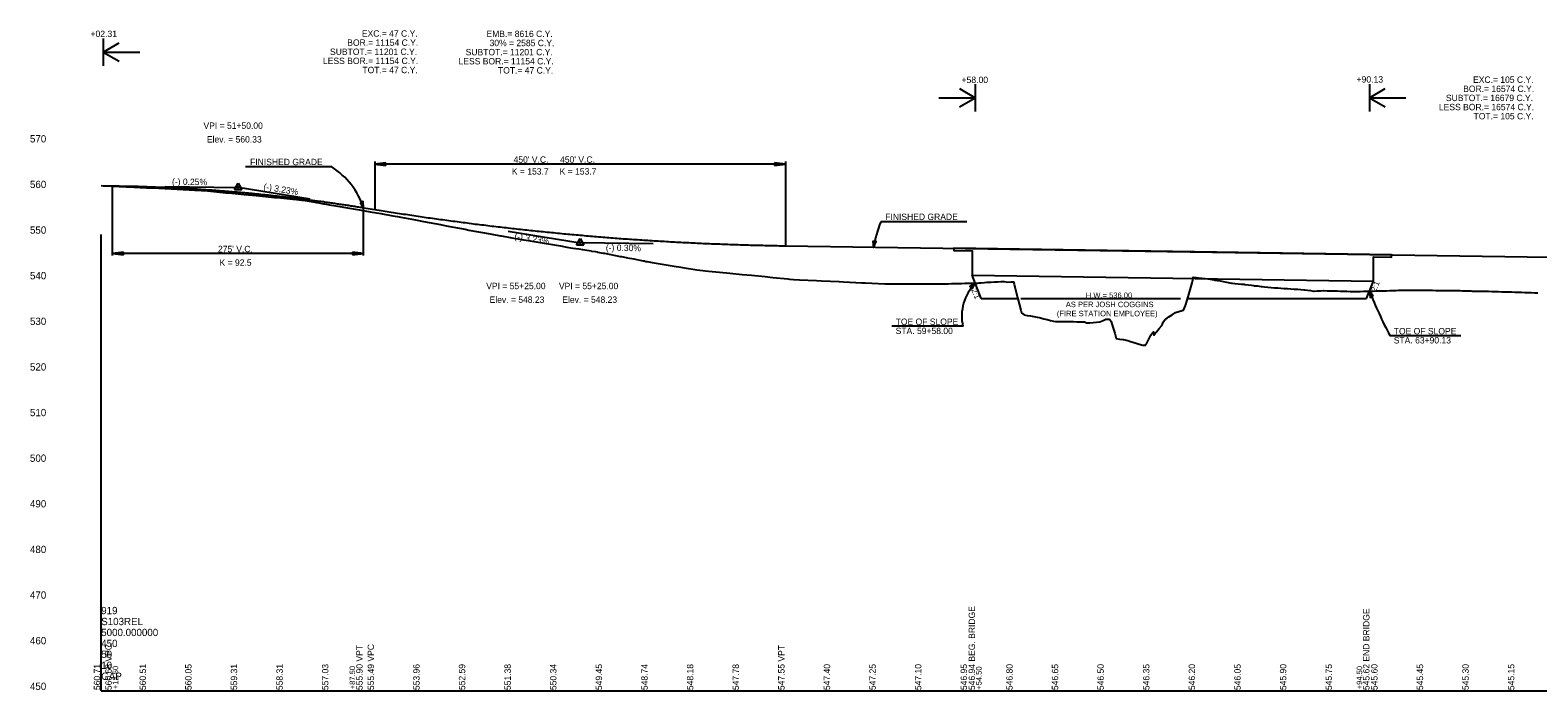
# Model space of a CAD drawing. Extents: x 49922 to 52614, y 49991 to 60509.
# Drawn here: x 49922 to 51575, y 52500 to 53224 of the extents above; entities that cross this region are included whole.
import ezdxf

# ---------------------------------------------------------------- set-up
doc = ezdxf.new("R2010")
doc.units = 0
for name, color, linetype in [('RD_DDB_ElevTX', 7, 'Continuous'), ('RD_DDB_GradeTX', 7, 'Continuous'), ('RD_DDB_Profile_EX', 7, 'Continuous'), ('RD_DDB_Profile_Lbl', 7, 'Continuous'), ('RD_DDB_Profile_PR', 7, 'Continuous'), ('RD_DDB_StripGrade', 7, 'Continuous'), ('RD_DDB_VCLbl', 7, 'Continuous'), ('RD_GPK_Profile_Cell', 7, 'Continuous'), ('RD_Sketch7', 7, 'Continuous'), ('RD_Sketch8', 7, 'Continuous'), ('RD_TX_Profile', 7, 'Continuous')]:
    doc.layers.add(name, color=color, linetype=linetype)

msp = doc.modelspace()

# ---------------------------------------------------------------- linework, layer by layer
at = {"layer": 'RD_DDB_GradeTX'}
for p, q in [((50070, 53052.7), (50150, 53051.7)), ((50146, 53049.4), (50150, 53056.3)), ((50150, 53056.3), (50154, 53049.4)), ((50229, 53038.9), (50150, 53051.7)), ((50146, 53049.4), (50154, 53049.4)), ((50446, 53003.9), (50525, 52991.1)), ((50521, 52988.8), (50525, 52995.7)), ((50521, 52988.8), (50529, 52988.8)), ((50525, 52995.7), (50529, 52988.8)), ((50605, 52989.9), (50525, 52991.1))]:
    msp.add_line(p, q, dxfattribs=at)
for centre in [(50150, 53051.7), (50525, 52991.1)]:
    msp.add_circle(centre, 0.529, dxfattribs=at)
at = {"layer": 'RD_DDB_Profile_EX'}
for points in [[(50000, 53053.7), (50004.7, 53053.4), (50027.3, 53052.4), (50029.1, 53052.3), (50049.8, 53051.4), (50052.3, 53051.3), (50053.5, 53051.2), (50056.5, 53051.1), (50063.1, 53050.8), (50069.8, 53050.5), (50076.5, 53050.1), (50077.3, 53050.1), (50077.7, 53050.1), (50083.2, 53049.8), (50085.9, 53049.7), (50089.9, 53049.5), (50096.5, 53049.2), (50102.6, 53048.8), (50103.2, 53048.8), (50109.9, 53048.4), (50111.8, 53048.3), (50113.2, 53048.2), (50116.6, 53047.9), (50123.3, 53047.2), (50130, 53046.6), (50136.7, 53045.9), (50139.3, 53045.7), (50143.3, 53045.3), (50150, 53044.7), (50156.7, 53044), (50161.6, 53043.5), (50163.4, 53043.4), (50165.7, 53043.2), (50170, 53042.8), (50176.7, 53042.1), (50183.4, 53041.4), (50186.6, 53041.1), (50190.1, 53040.8), (50192.3, 53040.6), (50196.8, 53040.2), (50203.4, 53039.5), (50210.1, 53038.9), (50211.5, 53038.7), (50214.2, 53038.5), (50216.8, 53038.2), (50219.8, 53037.9), (50223.5, 53037.3), (50230.2, 53036.2), (50236.1, 53035.3), (50236.8, 53035.1), (50243.5, 53033.9), (50244.8, 53033.7), (50250.2, 53032.8), (50259.5, 53031.3), (50269.8, 53029.4), (50283, 53027.3), (50294.8, 53025.1), (50306.4, 53023.2), (50319.8, 53020.7), (50324.6, 53019.8), (50328.3, 53019.2), (50344.6, 53016.2), (50353.2, 53014.4), (50371.8, 53011), (50378.2, 53009.7), (50399.1, 53005.8), (50403.1, 53005), (50426.5, 53000.7), (50428.1, 53000.4), (50437.7, 52998.6), (50438.3, 52998.6), (50444.7, 52997.5), (50450, 52996.6), (50456.7, 52995.4), (50462.7, 52994.4), (50463.4, 52994.3), (50468.3, 52993.5), (50470.1, 52993.1), (50476.8, 52992), (50483.4, 52990.9), (50487.6, 52990.2), (50490.1, 52989.8), (50496.8, 52988.7), (50498.9, 52988.3), (50503.5, 52987.6), (50510.2, 52986.4), (50512.5, 52986), (50516.9, 52985.3), (50523.5, 52984.3), (50527.7, 52983.6), (50530.2, 52983.2), (50536.9, 52982.1), (50537.5, 52982), (50541.9, 52981.3), (50543.6, 52981), (50544, 52980.9), (50550.3, 52979.8), (50551.6, 52979.5), (50556.9, 52978.5), (50563.6, 52977.1), (50569, 52976.1)], [(50569, 52976.1), (50570.3, 52975.9), (50575.3, 52974.9), (50577, 52974.6), (50583.7, 52973.3), (50590.3, 52972), (50594, 52971.3), (50595, 52971.1), (50597, 52970.7), (50598.6, 52970.4), (50603.9, 52969.5), (50610.4, 52968.4), (50617.1, 52967.3), (50623.7, 52966.2), (50630.4, 52965), (50633.3, 52964.6), (50637.1, 52963.9), (50643.8, 52962.8), (50648.4, 52962), (50650.7, 52961.6), (50652.7, 52961.3), (50665.5, 52960.1), (50677.7, 52958.9), (50689.1, 52957.8), (50702.7, 52956.4), (50712.7, 52955.5), (50727.7, 52954), (50736.2, 52953.1), (50752.7, 52951.5), (50754.5, 52951.3), (50758.9, 52950.9), (50765.5, 52950.6), (50783.9, 52949.7), (50789.5, 52949.5), (50808.9, 52948.5), (50813.5, 52948.3), (50833.9, 52947.3), (50837.5, 52947.2), (50859, 52946.1), (50859.3, 52946.1), (50862.3, 52945.9), (50864.8, 52946), (50887.2, 52945.9), (50895, 52946), (50912.2, 52946), (50921.2, 52946.2), (50923.2, 52946.2), (50924.8, 52946.2), (50928.4, 52946.2), (50932, 52946.3), (50935.6, 52946.3), (50937.2, 52946.3), (50939.2, 52946.4), (50942.9, 52946.5), (50946.5, 52946.6), (50950.1, 52946.7), (50951, 52946.7), (50953.7, 52946.8), (50957.3, 52946.8), (50960.9, 52946.9), (50962.2, 52947), (50963.5, 52947), (50964.5, 52947.1), (50968.1, 52947.5), (50970.8, 52947.8), (50971.7, 52947.8), (50975.4, 52948), (50979, 52948.2), (50982.6, 52948.4), (50986.2, 52948.5), (50988.7, 52948.7), (50989.8, 52948.7), (50993.6, 52948), (50997, 52948.1), (50998.7, 52948.1), (51000, 52948.2), (51000.6, 52945.5), (51001.3, 52942.5), (51004.3, 52931.1), (51007.9, 52917.1), (51008.6, 52914.3), (51011.6, 52912.1), (51015.1, 52911.4), (51018.7, 52910.8), (51022.3, 52910.1), (51025.9, 52909.4), (51028.3, 52909), (51029.5, 52908.7), (51033.1, 52907.8), (51036.8, 52906.9), (51040.4, 52906), (51044, 52905.1), (51045.9, 52904.6), (51047.6, 52904.7), (51051.2, 52904.7), (51054.8, 52904.7), (51055.6, 52904.7), (51058.4, 52904.6), (51062, 52904.6), (51065.6, 52904.6), (51069.3, 52904.5)], [(51069.3, 52904.5), (51072.9, 52904.5), (51076.5, 52904.4), (51077.9, 52904.4), (51080.1, 52903.4), (51083.8, 52903.2), (51087.3, 52903.5), (51091.1, 52903.9), (51094.7, 52904.3), (51098.2, 52905.9), (51101.3, 52907.3), (51101.8, 52907.3), (51104.8, 52907.5), (51105.4, 52906.9), (51107, 52904.9), (51109, 52898.6), (51111.1, 52891.8), (51112.4, 52886), (51116.2, 52885.5), (51119.8, 52885), (51120.7, 52884.9), (51122.4, 52884.7), (51123.4, 52884.4), (51125.3, 52883.8), (51127, 52883.3), (51130.7, 52882.2), (51134.3, 52881.2), (51137.9, 52880.1), (51141.7, 52878.9), (51144.6, 52878.7), (51145.1, 52879.4), (51145.7, 52880.3), (51148.7, 52886.2), (51150.5, 52889.7), (51152.3, 52892.2), (51153.4, 52893.6), (51153.9, 52889.7), (51155.9, 52892.6), (51156.7, 52893.6), (51159.5, 52897), (51162.5, 52900.5), (51163.2, 52901.9), (51164.2, 52903.9), (51165.6, 52906.1), (51166.2, 52906.9), (51166.8, 52907.3), (51170.4, 52909.7), (51174, 52912.1), (51177.7, 52914.5), (51181.2, 52915.7), (51184.8, 52916.8), (51185.9, 52917.1), (51186.3, 52917.2), (51188.4, 52922.3), (51188.9, 52923.5), (51192, 52934.4), (51195.7, 52947.1), (51196.6, 52950.5), (51196.8, 52953.2), (51199.3, 52953), (51200.3, 52953), (51202.9, 52952.7), (51206.5, 52952.3), (51210.1, 52951.9), (51213.1, 52951.6), (51213.7, 52951.5), (51217.3, 52950.9), (51220.1, 52950.4), (51221, 52950.2), (51223.6, 52949.7), (51224.6, 52949.6), (51228.2, 52948.9), (51231.8, 52948.3), (51235.4, 52947.6), (51239, 52946.9), (51239.4, 52946.8), (51240, 52946.7), (51242.6, 52946.5), (51246.2, 52946.1), (51249.8, 52945.8), (51253, 52945.5), (51253.4, 52945.4), (51257.1, 52944.9), (51260.7, 52944.5), (51263.6, 52944.1), (51264.3, 52944), (51267.9, 52943.7), (51269.1, 52943.6), (51271.5, 52943.3), (51272.4, 52943.2), (51275.1, 52942.9), (51278.7, 52942.5), (51282.3, 52942.1), (51285.9, 52941.7), (51286.7, 52941.7), (51289.6, 52941.5), (51293.2, 52941.3), (51296.8, 52941), (51300.4, 52940.8), (51304, 52940.6), (51307.6, 52940.3)], [(51307.6, 52940.3), (51310.6, 52940.1), (51311.2, 52940.1), (51311.6, 52940.1), (51314.8, 52939.8), (51318.5, 52939.6), (51319.4, 52939.5), (51322.1, 52939.2), (51325.7, 52938.6), (51328.8, 52938.1), (51329.4, 52938.1), (51332.9, 52938.3), (51336.5, 52938.5), (51339.7, 52938.6), (51340.1, 52938.6), (51343.7, 52938.5), (51347.3, 52938.4), (51351, 52938.3), (51352.6, 52938.3), (51354.6, 52938.2), (51358.2, 52938.1), (51361.8, 52938), (51365.4, 52937.9), (51369, 52937.8), (51372.6, 52937.7), (51376.3, 52937.6), (51379.8, 52937.8), (51383.5, 52937.9), (51386.7, 52938), (51387.1, 52938), (51390.7, 52938.1), (51394.3, 52938.1), (51397.9, 52938.2), (51401.2, 52938.3), (51401.5, 52938.3), (51405.1, 52938.4), (51408.7, 52938.5), (51412.4, 52938.7), (51416, 52938.8), (51419.6, 52938.9), (51421.9, 52939), (51422.3, 52939), (51423.2, 52939), (51426.8, 52939), (51430.4, 52939), (51434, 52939), (51437.6, 52939), (51441.2, 52939), (51442.8, 52939), (51444.9, 52939), (51447.4, 52939), (51448.5, 52939), (51452.1, 52939), (51455.7, 52939), (51459.3, 52939), (51462.9, 52938.9), (51463.7, 52938.9), (51466.5, 52938.9), (51470.1, 52938.9), (51472.5, 52938.8), (51474, 52938.8), (51476.2, 52938.8), (51477.4, 52938.8), (51481, 52938.7), (51484.6, 52938.6), (51488.2, 52938.6), (51489.6, 52938.6), (51491.8, 52938.5), (51495.4, 52938.4), (51499, 52938.2), (51501.2, 52938.2), (51502.6, 52938.1), (51506.2, 52938.1), (51509.9, 52938), (51513.5, 52938), (51517.1, 52937.9), (51519.1, 52937.9), (51520.7, 52937.9), (51524.3, 52937.7), (51526.2, 52937.7), (51527.9, 52937.6), (51528.9, 52937.6), (51529.7, 52937.6), (51531.5, 52937.5), (51535.1, 52937.4), (51538.8, 52937.3), (51542.4, 52937.2), (51546, 52937.1), (51549.6, 52937), (51551, 52937), (51553.2, 52936.9), (51554.7, 52936.9), (51556.8, 52936.8), (51560.4, 52936.7), (51564, 52936.6), (51567.6, 52936.5), (51571.3, 52936.3), (51574.9, 52936.2)]]:
    msp.add_lwpolyline(points, dxfattribs=at)
at = {"layer": 'RD_DDB_Profile_PR'}
for p, q in [((50002.3, 53053.6), (50012.5, 53053.4)), ((50287.5, 53029.5), (50300, 53027.5)), ((50750, 52987.8), (51796.9, 52972.1))]:
    msp.add_line(p, q, dxfattribs=at)
for points in [[(50012.5, 53053.4), (50018, 53053.3), (50023.5, 53053.2), (50029, 53053.1), (50034.5, 53053), (50040, 53052.9), (50045.5, 53052.7), (50051, 53052.5), (50056.5, 53052.3), (50062, 53052.1), (50067.5, 53051.9), (50073, 53051.7), (50078.5, 53051.4), (50084, 53051.1), (50089.5, 53050.8), (50095, 53050.5), (50100.5, 53050.2), (50106, 53049.9), (50111.5, 53049.5), (50117, 53049.1), (50122.5, 53048.8), (50128, 53048.3), (50133.5, 53047.9), (50139, 53047.5), (50144.5, 53047), (50150, 53046.6), (50155.5, 53046.1), (50161, 53045.6), (50166.5, 53045.1), (50172, 53044.5), (50177.5, 53044), (50183, 53043.4), (50188.5, 53042.8), (50194, 53042.2), (50199.5, 53041.6), (50205, 53041), (50210.5, 53040.3), (50216, 53039.6), (50221.5, 53039), (50227, 53038.3), (50232.5, 53037.5), (50238, 53036.8), (50243.5, 53036.1), (50249, 53035.3), (50254.5, 53034.5), (50260, 53033.7), (50265.5, 53032.9), (50271, 53032.1), (50276.5, 53031.2), (50282, 53030.4), (50287.5, 53029.5)], [(50300, 53027.5), (50309, 53026), (50318, 53024.6), (50327, 53023.2), (50336, 53021.9), (50345, 53020.5), (50354, 53019.2), (50363, 53017.9), (50372, 53016.7), (50381, 53015.5), (50390, 53014.3), (50399, 53013.1), (50408, 53011.9), (50417, 53010.8), (50426, 53009.7), (50435, 53008.6), (50444, 53007.6), (50453, 53006.6), (50462, 53005.6), (50471, 53004.6), (50480, 53003.7), (50489, 53002.8), (50498, 53001.9), (50507, 53001), (50516, 53000.2), (50525, 52999.4), (50534, 52998.6), (50543, 52997.8), (50552, 52997.1), (50561, 52996.4), (50570, 52995.7), (50579, 52995.1), (50588, 52994.5), (50597, 52993.9), (50606, 52993.3), (50615, 52992.8), (50624, 52992.2), (50633, 52991.7), (50642, 52991.3), (50651, 52990.8), (50660, 52990.4), (50669, 52990), (50678, 52989.7), (50687, 52989.4), (50696, 52989.1), (50705, 52988.8), (50714, 52988.5), (50723, 52988.3), (50732, 52988.1), (50741, 52987.9), (50750, 52987.8)]]:
    msp.add_spline(points, degree=3, dxfattribs=at)
at = {"layer": 'RD_DDB_VCLbl'}
for p, q in [((50300, 53080), (50300, 53027.5)), ((50312, 53078.8), (50300, 53077.3)), ((50300, 53077.5), (50750, 53077.5)), ((50300, 53077.3), (50312, 53075.8)), ((50312, 53075.8), (50312, 53078.8)), ((50750, 53077.3), (50738, 53078.8)), ((50738, 53078.8), (50738, 53075.8)), ((50738, 53075.8), (50750, 53077.3)), ((50750, 53080), (50750, 52987.8)), ((50012.5, 52977), (50012.5, 53053.4)), ((50287.5, 52977), (50287.5, 53029.5)), ((50024.5, 52980.9), (50012.5, 52979.4)), ((50012.5, 52979.5), (50287.5, 52979.5)), ((50012.5, 52979.4), (50024.5, 52977.9)), ((50024.5, 52977.9), (50024.5, 52980.9)), ((50287.5, 52979.4), (50275.5, 52980.9)), ((50275.5, 52980.9), (50275.5, 52977.9)), ((50287.5, 52979.4), (50275.5, 52980.9)), ((50275.5, 52980.9), (50275.5, 52977.9)), ((50275.5, 52977.9), (50287.5, 52979.4)), ((50275.5, 52977.9), (50287.5, 52979.4))]:
    msp.add_line(p, q, dxfattribs=at)
at = {"layer": 'RD_GPK_Profile_Cell'}
for q in [(50000, 53000), (52600, 52500), (50000, 52500)]:
    msp.add_line((50000, 52500), q, dxfattribs=at)
at = {"layer": 'RD_Sketch7'}
for p, q in [((50964.7, 52930), (50954.5, 52955.6)), ((51386.9, 52930), (51394.5, 52949)), ((50964.7, 52930), (51004.5, 52930)), ((51190.8, 52930), (51386.9, 52930))]:
    msp.add_line(p, q, dxfattribs=at)
at = {"layer": 'RD_Sketch8'}
msp.add_lwpolyline([(51414.5, 52977.8), (50934.5, 52985), (50934.5, 52982.5), (50954.5, 52982.2), (50954.5, 52955.6), (51394.5, 52949), (51394.5, 52975.6), (51414.5, 52975.3)], close=True, dxfattribs=at)
at = {"layer": 'RD_TX_Profile'}
for p, q in [((50002.3, 53215), (50002.3, 53185)), ((50002.3, 53200), (50019.6, 53210)), ((50002.3, 53200), (50019.6, 53190)), ((50002.3, 53200), (50042.3, 53200)), ((50918, 53150), (50958, 53150)), ((50940.7, 53160), (50958, 53150)), ((50940.7, 53140), (50958, 53150)), ((50958, 53165), (50958, 53135)), ((51390.1, 53165), (51390.1, 53135)), ((51390.1, 53150), (51407.5, 53160)), ((51390.1, 53150), (51407.5, 53140)), ((51390.1, 53150), (51430.1, 53150)), ((50252.8, 53074.1), (50158.2, 53074.1)), ((50948.9, 53014), (50854.4, 53014)), ((51008.1, 52930), (51183, 52930)), ((50944.4, 52899.5), (50866.5, 52899.5)), ((51490.5, 52889.2), (51412.6, 52889.2))]:
    msp.add_line(p, q, dxfattribs=at)
for points in [[(50283.7, 53035.2), (50287.5, 53029.4), (50287.1, 53036.3)], [(50845.9, 52992.8), (50846.7, 52985.9), (50849.5, 52992.3)], [(50954.6, 52940.7), (50958, 52946.9), (50952, 52943.3)], [(51394.3, 52932.5), (51390.1, 52938.1), (51391, 52931.1)]]:
    msp.add_lwpolyline(points, close=True, dxfattribs=at)
for centre, radius, start, end in [((50207.8, 53003.4), 83.8, 18.0396, 57.5215), ((50965.8, 52968.4), 120.3, 157.7492, 171.6417), ((50995.1, 52910.6), 51.8, 135.6457, 192.4205), ((51910.9, 53147.6), 561.4, 201.9147, 207.4042)]:
    msp.add_arc(centre, radius, start, end, dxfattribs=at)

# ---------------------------------------------------------------- texts
at = {"layer": 'RD_DDB_ElevTX'}
for s, p in [('570', (49921.9, 53101)), ('560', (49921.9, 53051)), ('550', (49921.9, 53001)), ('540', (49921.9, 52951)), ('530', (49921.9, 52901)), ('520', (49921.9, 52851)), ('510', (49921.9, 52801)), ('500', (49921.9, 52751)), ('490', (49921.9, 52701)), ('480', (49921.9, 52651)), ('470', (49921.9, 52601)), ('460', (49921.9, 52551)), ('450', (49921.9, 52501))]:
    msp.add_text(s, height=8, dxfattribs=at).set_placement(p)
at = {"layer": 'RD_DDB_GradeTX'}
for s, rotation, p in [('(-) 0.25%', 359.2719, (50077.5, 53054.6)), ('(-) 3.23%', 350.8305, (50177.4, 53049.3)), ('(-) 3.23%', 350.8305, (50452.5, 52995.1)), ('(-) 0.30%', 359.1406, (50553.1, 52982.3))]:
    msp.add_text(s, height=7, rotation=rotation, dxfattribs=at).set_placement(p)
at = {"layer": 'RD_DDB_Profile_Lbl'}
for s, p in [('VPI = 51+50.00', (50112.1, 53115.9)), ('Elev. = 560.33', (50115.8, 53100.9)), ('VPI = 55+25.00', (50422, 52940.2)), ('VPI = 55+25.00', (50501.7, 52940.2)), ('Elev. = 548.23', (50425.7, 52925.2)), ('Elev. = 548.23', (50505.4, 52925.2))]:
    msp.add_text(s, height=7, dxfattribs=at).set_placement(p)
at = {"layer": 'RD_DDB_StripGrade'}
for s, p in [('546.94 BEG. BRIDGE', (50957.8, 52500.8)), ('545.62 END BRIDGE', (51390.2, 52500.8)), ('560.68 VPC', (50011.5, 52500.8)), ('555.90 VPT', (50286.5, 52500.8)), ('555.49 VPC', (50299, 52500.8)), ('547.55 VPT', (50749, 52500.8)), ('560.71', (49998.9, 52500.8)), ('560.51', (50049, 52500.8)), ('560.05', (50099, 52500.8)), ('559.31', (50149, 52500.8)), ('558.31', (50199, 52500.8)), ('557.03', (50249, 52500.8)), ('555.49', (50299, 52500.8)), ('553.96', (50349, 52500.8)), ('552.59', (50399, 52500.8)), ('551.38', (50449, 52500.8)), ('550.34', (50499, 52500.8)), ('549.45', (50549, 52500.8)), ('548.74', (50599, 52500.8)), ('548.18', (50649, 52500.8)), ('547.78', (50699, 52500.8)), ('547.55', (50749, 52500.8)), ('547.40', (50799, 52500.8)), ('547.25', (50849, 52500.8)), ('547.10', (50899, 52500.8)), ('546.95', (50949, 52500.8)), ('546.80', (50999, 52500.8)), ('546.65', (51049, 52500.8)), ('546.50', (51099, 52500.8)), ('546.35', (51149, 52500.8)), ('546.20', (51199, 52500.8)), ('546.05', (51249, 52500.8)), ('545.90', (51299, 52500.8)), ('545.75', (51349, 52500.8)), ('545.60', (51399, 52500.8)), ('545.45', (51449, 52500.8)), ('545.30', (51499, 52500.8)), ('545.15', (51549, 52500.8))]:
    msp.add_text(s, height=7, rotation=90, dxfattribs=at).set_placement(p)
at = {"layer": 'RD_DDB_VCLbl'}
for s, p in [("450' V.C.", (50452, 53078.7)), ("450' V.C.", (50503, 53078.7)), ('K = 153.7', (50450.1, 53065.8)), ('K = 153.7', (50502.5, 53065.8)), ("275' V.C.", (50128, 52980.7)), ('K = 92.5', (50129.7, 52965.8))]:
    msp.add_text(s, height=7, dxfattribs=at).set_placement(p)
at = {"layer": 'RD_GPK_Profile_Cell'}
for s, p in [('919', (50000, 52584)), ('S103REL', (50000, 52572)), ('450', (50000, 52548)), ('5000.000000', (50000, 52560)), ('50', (50000, 52536)), ('10', (50000, 52524)), ('GAP', (50000, 52512))]:
    msp.add_text(s, height=8, dxfattribs=at).set_placement(p)
at = {"layer": 'RD_TX_Profile'}
for s, height, p in [('+02.31', 7.06, (49988.2, 53216.5)), ('EXC.= 47 C.Y.', 7, (50285.7, 53216.9)), ('EMB.= 8616 C.Y.', 7, (50422.3, 53216.5)), ('SUBTOT.= 11201 C.Y.', 7, (50250.8, 53196.9)), ('BOR.= 11154 C.Y.', 7, (50269.7, 53206.9)), ('SUBTOT.= 11201 C.Y.', 7, (50399.5, 53196.5)), ('30% = 2585 C.Y.', 7, (50425.7, 53206.5)), ('LESS BOR.= 11154 C.Y.', 7, (50243.1, 53186.9)), ('TOT.= 47 C.Y.', 7, (50286.3, 53176.9)), ('LESS BOR.= 11154 C.Y.', 7, (50391.7, 53186.5)), ('TOT.= 47 C.Y.', 7, (50434.9, 53176.5)), ('+58.00', 7.06, (50943, 53166.1)), ('+90.13', 7.06, (51376, 53166.6)), ('EXC.= 105 C.Y.', 7, (51503.7, 53166.3)), ('SUBTOT.= 16679 C.Y.', 7, (51474, 53146.3)), ('BOR.= 16574 C.Y.', 7, (51492.9, 53156.3)), ('LESS BOR.= 16574 C.Y.', 7, (51466.3, 53136.3)), ('TOT.= 105 C.Y.', 7, (51504.3, 53126.3)), ('FINISHED GRADE', 7, (50163.2, 53076.1)), ('FINISHED GRADE', 7, (50859.4, 53016)), ('H.W.= 536.00', 6, (51079.2, 52930.5)), ('AS PER JOSH COGGINS', 6, (51057.3, 52920.5)), ('TOE OF SLOPE', 7, (50870.8, 52901)), ('(FIRE STATION EMPLOYEE)', 6, (51047.5, 52910.5)), ('STA. 59+58.00', 7, (50870.8, 52891)), ('TOE OF SLOPE', 7, (51416.8, 52890.7)), ('STA. 63+90.13', 7, (51416.8, 52880.7))]:
    msp.add_text(s, height=height, dxfattribs=at).set_placement(p)
for s, rotation, p in [('2:1', 291.8014, (50953.7, 52939.5)), ('2:1', 68.1986, (51397.2, 52936.8)), ('+12.50', 90, (50018.6, 52501.8)), ('+87.50', 90, (50278.3, 52501.7)), ('+54.50', 90, (50965, 52501.2)), ('+94.50', 90, (51382.2, 52501.7))]:
    msp.add_text(s, height=6, rotation=rotation, dxfattribs=at).set_placement(p)

doc.saveas('drawing.dxf')
